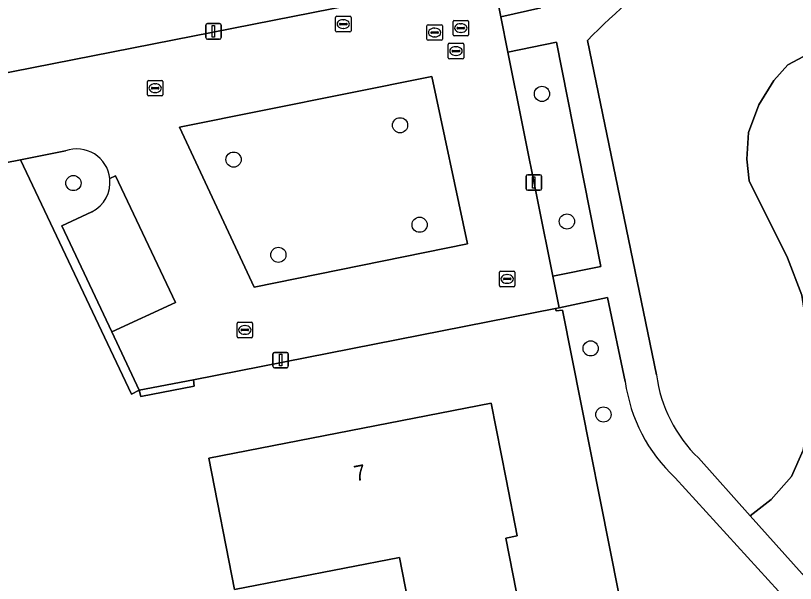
# Model space of a CAD drawing. Extents: x 157648 to 158502, y 379212 to 380938.
# Drawn here: x 158214.5 to 158264.7, y 380182.1 to 380218.7 of the extents above; entities that cross this region are included whole.
import ezdxf

# ---------------------------------------------------------------- set-up
doc = ezdxf.new("R2010")
doc.units = 0
for name, color, linetype in [('IMGEO_Boom', 7, 'Continuous'), ('IMGEO_Brandkraan', 7, 'Continuous'), ('IMGEO_Erf', 7, 'Continuous'), ('IMGEO_Groenvoorziening', 7, 'Continuous'), ('IMGEO_Kolk', 7, 'Continuous'), ('IMGEO_Lichtmast', 7, 'Continuous'), ('IMGEO_Pand', 7, 'Continuous'), ('IMGEO_Pand_nummerreeks', 7, 'Continuous'), ('IMGEO_Parkeervlak_open', 7, 'Continuous'), ('IMGEO_Rijbaan_lokaal_open', 7, 'Continuous'), ('IMGEO_Rioolput', 7, 'Continuous'), ('IMGEO_Voetpad_halfverhard', 7, 'Continuous'), ('IMGEO_Voetpad_open', 7, 'Continuous')]:
    doc.layers.add(name, color=color, linetype=linetype)

msp = doc.modelspace()

# ---------------------------------------------------------------- linework, layer by layer
at = {"layer": 'IMGEO_Boom'}
for centre in [(158248.407, 380213.7), (158239.266, 380211.678), (158228.543, 380209.465), (158218.227, 380207.953), (158240.525, 380205.265), (158250.013, 380205.478), (158231.428, 380203.323), (158251.542, 380197.294), (158252.365, 380193.03)]:
    msp.add_circle(centre, 0.489, dxfattribs=at)
at = {"layer": 'IMGEO_Brandkraan'}
for p, q in [((158235.183, 380218.701), (158236.035, 380218.701)), ((158235.108, 380217.775), (158235.108, 380218.627)), ((158235.367, 380218.195), (158235.367, 380218.207)), ((158235.805, 380218.158), (158235.407, 380218.158)), ((158235.41, 380218.244), (158235.808, 380218.244)), ((158235.596, 380218.481), (158235.621, 380218.481)), ((158235.851, 380218.207), (158235.851, 380218.195)), ((158236.109, 380218.627), (158236.109, 380217.775)), ((158236.035, 380217.701), (158235.183, 380217.701)), ((158235.619, 380217.921), (158235.594, 380217.921))]:
    msp.add_line(p, q, dxfattribs=at)
for points in [[(158235.183, 380218.701), (158236.035, 380218.701)], [(158235.108, 380217.775), (158235.108, 380218.627)], [(158236.109, 380218.627), (158236.109, 380217.775)], [(158236.035, 380217.701), (158235.183, 380217.701)]]:
    msp.add_lwpolyline(points, dxfattribs=at)
for centre, radius, start, end in [((158235.185, 380218.625), 0.0765, 91.552, 178.448), ((158235.185, 380218.625), 0.0765, 91.552, 178.448), ((158236.033, 380218.625), 0.0765, 1.552, 88.448), ((158236.033, 380218.625), 0.0765, 1.552, 88.448), ((158235.407, 380218.204), 0.0403, 85.8775, 175.7526), ((158235.404, 380218.194), 0.0366, 178.938, 274.7102), ((158235.808, 380218.201), 0.043, 264.8664, 352.4533), ((158235.812, 380218.206), 0.0386, 1.7309, 96.639), ((158235.185, 380217.777), 0.0765, 181.552, 268.448), ((158235.185, 380217.777), 0.0765, 181.552, 268.448), ((158236.033, 380217.777), 0.0765, 271.552, 358.448), ((158236.033, 380217.777), 0.0765, 271.552, 358.448)]:
    msp.add_arc(centre, radius, start, end, dxfattribs=at)
for centre, major_axis, ratio, start_param, end_param in [((158235.595, 380218.201), (-0.387, 0.002), 0.722429, 4.712389, 7.853982), ((158235.62, 380218.201), (-0.39, 0.002), 0.717154, 1.570796, 4.712389)]:
    msp.add_ellipse(centre, major_axis=major_axis, ratio=ratio, start_param=start_param, end_param=end_param, dxfattribs=at)
at = {"layer": 'IMGEO_Erf'}
for points in [[(158166.582, 380206.823), (158169.582, 380202.726), (158169.797, 380202.917), (158190.532, 380210.271), (158193.686, 380211.088), (158245.234, 380221.247), (158243.431, 380250)], [(158253.955, 380178.433), (158249.732, 380199.752), (158249.31, 380199.723), (158249.282, 380199.871), (158225.953, 380195.277), (158226.014, 380194.869), (158222.575, 380194.188), (158222.466, 380194.594), (158221.97, 380194.353), (158214.817, 380209.454), (158195.034, 380205.584)]]:
    msp.add_lwpolyline(points, dxfattribs=at)
msp.add_lwpolyline([(158226.941, 380190.21), (158245.144, 380193.768), (158246.103, 380188.861), (158246.816, 380185.212), (158246.089, 380185.07), (158247.655, 380177.059), (158247.432, 380177.014), (158247.828, 380174.987), (158248.778, 380175.171), (158249.944, 380169.206), (158229.771, 380165.263), (158226.238, 380164.572), (158225.516, 380168.269), (158224.557, 380173.176), (158228.089, 380173.866), (158240.698, 380176.33), (158239.234, 380183.819), (158228.596, 380181.74)], close=True, dxfattribs=at)
at = {"layer": 'IMGEO_Groenvoorziening'}
for points in [[(158252.678, 380280.756), (158247.042, 380309.288), (158241.64, 380308.242), (158248.984, 380270.917), (158242.787, 380260.656), (158243.431, 380250), (158245.234, 380221.247), (158245.754, 380218.66), (158248.342, 380219.248)], [(158258.488, 380190.228), (158261.824, 380186.49), (158263.178, 380187.562), (158264.483, 380189.025), (158265.228, 380190.728), (158265.591, 380192.798), (158265.699, 380195.528), (158265.541, 380198.206), (158265.141, 380200.731), (158264.222, 380203.141), (158261.76, 380208.086), (158261.592, 380209.494), (158261.702, 380211.208), (158262.371, 380213), (158263.345, 380214.564), (158264.244, 380215.582), (158265.258, 380216.118), (158266.388, 380215.994), (158268.332, 380215.25), (158269.273, 380214.478), (158287.12, 380217.687), (158283.852, 380234.352), (158264.079, 380226.385)], [(158251.342, 380217.148), (158255.784, 380195.591)], [(158253.767, 380195.154), (158252.625, 380200.572), (158249.521, 380199.918), (158249.282, 380199.871), (158249.31, 380199.723), (158249.732, 380199.752), (158253.955, 380178.433)], [(158264.303, 380180.919), (158256.98, 380188.955)]]:
    msp.add_lwpolyline(points, dxfattribs=at)
for points in [[(158287.12, 380217.687), (158269.273, 380214.478), (158268.332, 380215.25), (158266.388, 380215.994), (158265.258, 380216.118), (158264.244, 380215.582), (158263.345, 380214.564), (158262.371, 380213), (158261.702, 380211.208), (158261.592, 380209.494), (158261.76, 380208.086), (158264.222, 380203.141), (158265.141, 380200.731), (158265.541, 380198.206), (158265.699, 380195.528), (158265.591, 380192.798), (158265.228, 380190.728), (158264.483, 380189.025), (158263.178, 380187.562), (158261.824, 380186.49), (158265.157, 380182.756), (158273.123, 380184.264), (158268.358, 380209.436), (158287.935, 380213.528)], [(158249.113, 380201.945), (158252.188, 380202.564), (158249.337, 380217.041), (158246.209, 380216.392)]]:
    msp.add_lwpolyline(points, close=True, dxfattribs=at)
for centre, radius, start, end in [((158285.034, 380184.09), 47.202, 116.356, 135.544), ((158264.739, 380196.743), 9.028, 187.3291, 226.185), ((158264.056, 380196.554), 10.383, 187.7515, 227.0447)]:
    msp.add_arc(centre, radius, start, end, dxfattribs=at)
at = {"layer": 'IMGEO_Kolk'}
for p, q in [((158242.681, 380217.517), (158242.681, 380218.369)), ((158242.756, 380218.443), (158243.608, 380218.443)), ((158243.169, 380218.223), (158243.194, 380218.223)), ((158243.682, 380218.369), (158243.682, 380217.517)), ((158242.94, 380217.937), (158242.94, 380217.949)), ((158243.378, 380217.9), (158242.98, 380217.9)), ((158242.983, 380217.986), (158243.381, 380217.986)), ((158243.192, 380217.663), (158243.167, 380217.663)), ((158243.424, 380217.949), (158243.424, 380217.937)), ((158243.608, 380217.443), (158242.756, 380217.443)), ((158222.991, 380213.644), (158222.991, 380214.496)), ((158223.066, 380214.57), (158223.918, 380214.57)), ((158223.479, 380214.35), (158223.504, 380214.35)), ((158223.992, 380214.496), (158223.992, 380213.644)), ((158223.25, 380214.064), (158223.25, 380214.076)), ((158223.688, 380214.027), (158223.29, 380214.027)), ((158223.293, 380214.113), (158223.691, 380214.113)), ((158223.502, 380213.79), (158223.477, 380213.79)), ((158223.734, 380214.076), (158223.734, 380214.064)), ((158223.918, 380213.57), (158223.066, 380213.57)), ((158245.661, 380201.346), (158245.661, 380202.198)), ((158245.736, 380202.272), (158246.588, 380202.272)), ((158246.662, 380202.198), (158246.662, 380201.346)), ((158245.92, 380201.766), (158245.92, 380201.778)), ((158246.358, 380201.729), (158245.96, 380201.729)), ((158245.963, 380201.815), (158246.361, 380201.815)), ((158246.149, 380202.052), (158246.174, 380202.052)), ((158246.404, 380201.778), (158246.404, 380201.766)), ((158246.588, 380201.272), (158245.736, 380201.272)), ((158246.172, 380201.492), (158246.147, 380201.492)), ((158228.769, 380198.057), (158228.769, 380198.909)), ((158228.844, 380198.983), (158229.696, 380198.983)), ((158229.257, 380198.763), (158229.282, 380198.763)), ((158229.77, 380198.909), (158229.77, 380198.057)), ((158229.028, 380198.477), (158229.028, 380198.489)), ((158229.466, 380198.44), (158229.068, 380198.44)), ((158229.071, 380198.526), (158229.469, 380198.526)), ((158229.28, 380198.203), (158229.255, 380198.203)), ((158229.512, 380198.489), (158229.512, 380198.477)), ((158229.696, 380197.983), (158228.844, 380197.983))]:
    msp.add_line(p, q, dxfattribs=at)
for points in [[(158242.681, 380217.517), (158242.681, 380218.369)], [(158242.756, 380218.443), (158243.608, 380218.443)], [(158243.682, 380218.369), (158243.682, 380217.517)], [(158243.608, 380217.443), (158242.756, 380217.443)], [(158222.991, 380213.644), (158222.991, 380214.496)], [(158223.066, 380214.57), (158223.918, 380214.57)], [(158223.992, 380214.496), (158223.992, 380213.644)], [(158223.918, 380213.57), (158223.066, 380213.57)], [(158245.661, 380201.346), (158245.661, 380202.198)], [(158245.736, 380202.272), (158246.588, 380202.272)], [(158246.662, 380202.198), (158246.662, 380201.346)], [(158246.588, 380201.272), (158245.736, 380201.272)], [(158228.769, 380198.057), (158228.769, 380198.909)], [(158228.844, 380198.983), (158229.696, 380198.983)], [(158229.77, 380198.909), (158229.77, 380198.057)], [(158229.696, 380197.983), (158228.844, 380197.983)]]:
    msp.add_lwpolyline(points, dxfattribs=at)
for centre, radius, start, end in [((158242.758, 380218.367), 0.0765, 91.552, 178.448), ((158242.758, 380218.367), 0.0765, 91.552, 178.448), ((158243.606, 380218.367), 0.0765, 1.552, 88.448), ((158243.606, 380218.367), 0.0765, 1.552, 88.448), ((158242.98, 380217.946), 0.0403, 85.8775, 175.7526), ((158242.977, 380217.936), 0.0366, 178.938, 274.7102), ((158243.381, 380217.943), 0.043, 264.8664, 352.4533), ((158243.385, 380217.948), 0.0386, 1.7309, 96.639), ((158242.758, 380217.519), 0.0765, 181.552, 268.448), ((158242.758, 380217.519), 0.0765, 181.552, 268.448), ((158243.606, 380217.519), 0.0765, 271.552, 358.448), ((158243.606, 380217.519), 0.0765, 271.552, 358.448), ((158223.068, 380214.494), 0.0765, 91.552, 178.448), ((158223.068, 380214.494), 0.0765, 91.552, 178.448), ((158223.916, 380214.494), 0.0765, 1.552, 88.448), ((158223.916, 380214.494), 0.0765, 1.552, 88.448), ((158223.068, 380213.646), 0.0765, 181.552, 268.448), ((158223.068, 380213.646), 0.0765, 181.552, 268.448), ((158223.29, 380214.073), 0.0403, 85.8775, 175.7526), ((158223.287, 380214.063), 0.0366, 178.938, 274.7102), ((158223.691, 380214.07), 0.043, 264.8664, 352.4533), ((158223.695, 380214.075), 0.0386, 1.7309, 96.639), ((158223.916, 380213.646), 0.0765, 271.552, 358.448), ((158223.916, 380213.646), 0.0765, 271.552, 358.448), ((158245.738, 380202.196), 0.0765, 91.552, 178.448), ((158245.738, 380202.196), 0.0765, 91.552, 178.448), ((158246.586, 380202.196), 0.0765, 1.552, 88.448), ((158246.586, 380202.196), 0.0765, 1.552, 88.448), ((158245.96, 380201.775), 0.0403, 85.8775, 175.7526), ((158245.957, 380201.765), 0.0366, 178.938, 274.7102), ((158246.361, 380201.772), 0.043, 264.8664, 352.4533), ((158246.365, 380201.777), 0.0386, 1.7309, 96.639), ((158245.738, 380201.348), 0.0765, 181.552, 268.448), ((158245.738, 380201.348), 0.0765, 181.552, 268.448), ((158246.586, 380201.348), 0.0765, 271.552, 358.448), ((158246.586, 380201.348), 0.0765, 271.552, 358.448), ((158228.846, 380198.907), 0.0765, 91.552, 178.448), ((158228.846, 380198.907), 0.0765, 91.552, 178.448), ((158229.694, 380198.907), 0.0765, 1.552, 88.448), ((158229.694, 380198.907), 0.0765, 1.552, 88.448), ((158229.068, 380198.486), 0.0403, 85.8775, 175.7526), ((158229.065, 380198.476), 0.0366, 178.938, 274.7102), ((158229.469, 380198.483), 0.043, 264.8664, 352.4533), ((158229.473, 380198.488), 0.0386, 1.7309, 96.639), ((158228.846, 380198.059), 0.0765, 181.552, 268.448), ((158228.846, 380198.059), 0.0765, 181.552, 268.448), ((158229.694, 380198.059), 0.0765, 271.552, 358.448), ((158229.694, 380198.059), 0.0765, 271.552, 358.448)]:
    msp.add_arc(centre, radius, start, end, dxfattribs=at)
for centre, major_axis, ratio, start_param, end_param in [((158243.168, 380217.943), (-0.387, 0.002), 0.722429, 4.712389, 7.853982), ((158243.193, 380217.943), (-0.39, 0.002), 0.717154, 1.570796, 4.712389), ((158223.478, 380214.07), (-0.387, 0.002), 0.722429, 4.712389, 7.853982), ((158223.503, 380214.07), (-0.39, 0.002), 0.717154, 1.570796, 4.712389), ((158246.148, 380201.772), (-0.387, 0.002), 0.722429, 4.712389, 7.853982), ((158246.173, 380201.772), (-0.39, 0.002), 0.717154, 1.570796, 4.712389), ((158229.256, 380198.483), (-0.387, 0.002), 0.722429, 4.712389, 7.853982), ((158229.281, 380198.483), (-0.39, 0.002), 0.717154, 1.570796, 4.712389)]:
    msp.add_ellipse(centre, major_axis=major_axis, ratio=ratio, start_param=start_param, end_param=end_param, dxfattribs=at)
at = {"layer": 'IMGEO_Lichtmast'}
for p, q in [((158226.854, 380218.23), (158227.644, 380218.23)), ((158227.644, 380218.23), (158226.854, 380218.23)), ((158226.754, 380217.33), (158226.754, 380218.13)), ((158226.754, 380218.13), (158226.754, 380217.33)), ((158227.744, 380218.13), (158227.744, 380217.33)), ((158227.744, 380217.33), (158227.744, 380218.13)), ((158227.644, 380217.23), (158226.854, 380217.23)), ((158226.854, 380217.23), (158227.644, 380217.23)), ((158247.386, 380207.588), (158247.386, 380208.388)), ((158247.386, 380208.388), (158247.386, 380207.588)), ((158247.486, 380208.488), (158248.276, 380208.488)), ((158248.276, 380208.488), (158247.486, 380208.488)), ((158248.376, 380208.388), (158248.376, 380207.588)), ((158248.376, 380207.588), (158248.376, 380208.388)), ((158248.276, 380207.488), (158247.486, 380207.488)), ((158247.486, 380207.488), (158248.276, 380207.488)), ((158231.075, 380196.139), (158231.075, 380196.939)), ((158231.075, 380196.939), (158231.075, 380196.139)), ((158231.175, 380197.039), (158231.965, 380197.039)), ((158231.965, 380197.039), (158231.175, 380197.039)), ((158232.065, 380196.939), (158232.065, 380196.139)), ((158232.065, 380196.139), (158232.065, 380196.939)), ((158231.965, 380196.039), (158231.175, 380196.039)), ((158231.175, 380196.039), (158231.965, 380196.039))]:
    msp.add_line(p, q, dxfattribs=at)
for points in [[(158227.174, 380218.105), (158227.324, 380218.105), (158227.324, 380217.355), (158227.174, 380217.355), (158227.174, 380218.105)], [(158247.806, 380208.363), (158247.956, 380208.363), (158247.956, 380207.613), (158247.806, 380207.613), (158247.806, 380208.363)], [(158231.495, 380196.914), (158231.645, 380196.914), (158231.645, 380196.164), (158231.495, 380196.164), (158231.495, 380196.914)]]:
    msp.add_lwpolyline(points, dxfattribs=at)
for centre, start, end in [((158226.854, 380218.13), 90, 180), ((158226.854, 380218.13), 90, 180), ((158227.644, 380218.13), 0, 90), ((158227.644, 380218.13), 360, 90), ((158226.854, 380217.33), 180, 270), ((158226.854, 380217.33), 180, 270), ((158227.644, 380217.33), 270, 0), ((158227.644, 380217.33), 270, 0), ((158247.486, 380208.388), 90, 180), ((158247.486, 380208.388), 90, 180), ((158248.276, 380208.388), 0, 90), ((158248.276, 380208.388), 360, 90), ((158247.486, 380207.588), 180, 270), ((158247.486, 380207.588), 180, 270), ((158248.276, 380207.588), 270, 0), ((158248.276, 380207.588), 270, 0), ((158231.175, 380196.939), 90, 180), ((158231.175, 380196.939), 90, 180), ((158231.965, 380196.939), 0, 90), ((158231.965, 380196.939), 360, 90), ((158231.175, 380196.139), 180, 270), ((158231.175, 380196.139), 180, 270), ((158231.965, 380196.139), 270, 0), ((158231.965, 380196.139), 270, 0)]:
    msp.add_arc(centre, 0.1, start, end, dxfattribs=at)
at = {"layer": 'IMGEO_Pand'}
msp.add_lwpolyline([(158246.103, 380188.861), (158245.144, 380193.768), (158226.941, 380190.21), (158228.596, 380181.74), (158239.234, 380183.819), (158240.698, 380176.33), (158228.089, 380173.866), (158224.557, 380173.176), (158225.516, 380168.269), (158226.238, 380164.572), (158229.771, 380165.263), (158249.944, 380169.206), (158248.778, 380175.171), (158247.828, 380174.987), (158247.432, 380177.014), (158247.655, 380177.059), (158246.089, 380185.07), (158246.816, 380185.212)], close=True, dxfattribs=at)
at = {"layer": 'IMGEO_Parkeervlak_open'}
msp.add_lwpolyline([(158229.866, 380201.236), (158243.614, 380204.045), (158241.321, 380214.817), (158225.062, 380211.566)], close=True, dxfattribs=at)
msp.add_lwpolyline([(158219.415, 380206.095), (158217.482, 380205.197), (158220.699, 380198.36), (158224.796, 380200.25), (158220.945, 380208.427), (158220.569, 380208.252)], dxfattribs=at)
msp.add_arc((158218.435, 380208.006), 2.148, 297.1399, 6.5664, dxfattribs=at)
at = {"layer": 'IMGEO_Rijbaan_lokaal_open'}
for points in [[(158246.209, 380216.392), (158245.754, 380218.66), (158245.234, 380221.247), (158193.686, 380211.088), (158190.532, 380210.271), (158169.797, 380202.917), (158173.283, 380198.101), (158191.21, 380204.483)], [(158220.569, 380208.252), (158220.945, 380208.427), (158224.796, 380200.25), (158220.699, 380198.36), (158222.466, 380194.594), (158225.953, 380195.277), (158249.282, 380199.871), (158249.521, 380199.918), (158249.113, 380201.945), (158246.209, 380216.392)], [(158195.034, 380205.584), (158214.817, 380209.454), (158217.726, 380210.037)]]:
    msp.add_lwpolyline(points, dxfattribs=at)
msp.add_lwpolyline([(158225.062, 380211.566), (158241.321, 380214.817), (158243.614, 380204.045), (158229.866, 380201.236)], close=True, dxfattribs=at)
msp.add_arc((158218.434, 380208.009), 2.149, 6.5071, 109.2469, dxfattribs=at)
at = {"layer": 'IMGEO_Rioolput'}
for p, q in [((158241.067, 380218.157), (158241.919, 380218.157)), ((158240.992, 380217.231), (158240.992, 380218.083)), ((158241.251, 380217.651), (158241.251, 380217.663)), ((158241.294, 380217.7), (158241.692, 380217.7)), ((158241.48, 380217.937), (158241.505, 380217.937)), ((158241.735, 380217.663), (158241.735, 380217.651)), ((158241.993, 380218.083), (158241.993, 380217.231)), ((158241.919, 380217.157), (158241.067, 380217.157)), ((158241.689, 380217.614), (158241.291, 380217.614)), ((158241.503, 380217.377), (158241.478, 380217.377)), ((158242.369, 380216.035), (158242.369, 380216.887)), ((158242.444, 380216.961), (158243.296, 380216.961)), ((158242.857, 380216.741), (158242.882, 380216.741)), ((158243.37, 380216.887), (158243.37, 380216.035)), ((158242.628, 380216.455), (158242.628, 380216.467)), ((158243.066, 380216.418), (158242.668, 380216.418)), ((158242.671, 380216.504), (158243.069, 380216.504)), ((158242.88, 380216.181), (158242.855, 380216.181)), ((158243.112, 380216.467), (158243.112, 380216.455)), ((158243.296, 380215.961), (158242.444, 380215.961))]:
    msp.add_line(p, q, dxfattribs=at)
for points in [[(158241.067, 380218.157), (158241.919, 380218.157)], [(158240.992, 380217.231), (158240.992, 380218.083)], [(158241.993, 380218.083), (158241.993, 380217.231)], [(158241.919, 380217.157), (158241.067, 380217.157)], [(158242.369, 380216.035), (158242.369, 380216.887)], [(158242.444, 380216.961), (158243.296, 380216.961)], [(158243.37, 380216.887), (158243.37, 380216.035)], [(158243.296, 380215.961), (158242.444, 380215.961)]]:
    msp.add_lwpolyline(points, dxfattribs=at)
for centre, radius, start, end in [((158241.069, 380218.081), 0.0765, 91.552, 178.448), ((158241.069, 380218.081), 0.0765, 91.552, 178.448), ((158241.917, 380218.081), 0.0765, 1.552, 88.448), ((158241.917, 380218.081), 0.0765, 1.552, 88.448), ((158241.291, 380217.66), 0.0403, 85.8775, 175.7526), ((158241.696, 380217.662), 0.0386, 1.7309, 96.639), ((158241.069, 380217.233), 0.0765, 181.552, 268.448), ((158241.069, 380217.233), 0.0765, 181.552, 268.448), ((158241.288, 380217.65), 0.0366, 178.938, 274.7102), ((158241.692, 380217.657), 0.043, 264.8664, 352.4533), ((158241.917, 380217.233), 0.0765, 271.552, 358.448), ((158241.917, 380217.233), 0.0765, 271.552, 358.448), ((158242.446, 380216.885), 0.0765, 91.552, 178.448), ((158242.446, 380216.885), 0.0765, 91.552, 178.448), ((158243.294, 380216.885), 0.0765, 1.552, 88.448), ((158243.294, 380216.885), 0.0765, 1.552, 88.448), ((158242.668, 380216.464), 0.0403, 85.8775, 175.7526), ((158242.665, 380216.454), 0.0366, 178.938, 274.7102), ((158243.069, 380216.461), 0.043, 264.8664, 352.4533), ((158243.073, 380216.466), 0.0386, 1.7309, 96.639), ((158242.446, 380216.037), 0.0765, 181.552, 268.448), ((158242.446, 380216.037), 0.0765, 181.552, 268.448), ((158243.294, 380216.037), 0.0765, 271.552, 358.448), ((158243.294, 380216.037), 0.0765, 271.552, 358.448)]:
    msp.add_arc(centre, radius, start, end, dxfattribs=at)
for centre, major_axis, ratio, start_param, end_param in [((158241.479, 380217.657), (-0.387, 0.002), 0.722429, 4.712389, 7.853982), ((158241.504, 380217.657), (-0.39, 0.002), 0.717154, 1.570796, 4.712389), ((158242.856, 380216.461), (-0.387, 0.002), 0.722429, 4.712389, 7.853982), ((158242.881, 380216.461), (-0.39, 0.002), 0.717154, 1.570796, 4.712389)]:
    msp.add_ellipse(centre, major_axis=major_axis, ratio=ratio, start_param=start_param, end_param=end_param, dxfattribs=at)
at = {"layer": 'IMGEO_Voetpad_halfverhard'}
for points in [[(158248.342, 380219.248), (158245.754, 380218.66), (158246.209, 380216.392), (158249.337, 380217.041), (158252.188, 380202.564), (158249.113, 380201.945), (158249.521, 380199.918), (158252.625, 380200.572), (158253.767, 380195.154)], [(158255.784, 380195.591), (158251.342, 380217.148)], [(158266.916, 380180.972), (158265.815, 380182.146), (158265.157, 380182.756), (158261.824, 380186.49), (158258.488, 380190.228)], [(158256.98, 380188.955), (158264.303, 380180.919)]]:
    msp.add_lwpolyline(points, dxfattribs=at)
for centre, radius, start, end in [((158285.034, 380184.09), 47.202, 116.356, 135.544), ((158264.739, 380196.743), 9.028, 187.3291, 226.185), ((158264.056, 380196.554), 10.383, 187.7515, 227.0447)]:
    msp.add_arc(centre, radius, start, end, dxfattribs=at)
at = {"layer": 'IMGEO_Voetpad_open'}
msp.add_lwpolyline([(158217.726, 380210.037), (158214.817, 380209.454), (158221.97, 380194.353), (158222.466, 380194.594), (158220.699, 380198.36), (158217.482, 380205.197), (158219.415, 380206.095)], dxfattribs=at)
msp.add_lwpolyline([(158225.953, 380195.277), (158222.466, 380194.594), (158222.575, 380194.188), (158226.014, 380194.869)], close=True, dxfattribs=at)
for centre, radius, start, end in [((158218.434, 380208.009), 2.149, 6.5071, 109.2469), ((158218.435, 380208.006), 2.148, 297.1399, 6.5664)]:
    msp.add_arc(centre, radius, start, end, dxfattribs=at)

# ---------------------------------------------------------------- texts
at = {"layer": 'IMGEO_Pand_nummerreeks'}
msp.add_text('7', height=1, rotation=11.0597, dxfattribs=at).set_placement((158236.401, 380188.718))

doc.saveas('drawing.dxf')
